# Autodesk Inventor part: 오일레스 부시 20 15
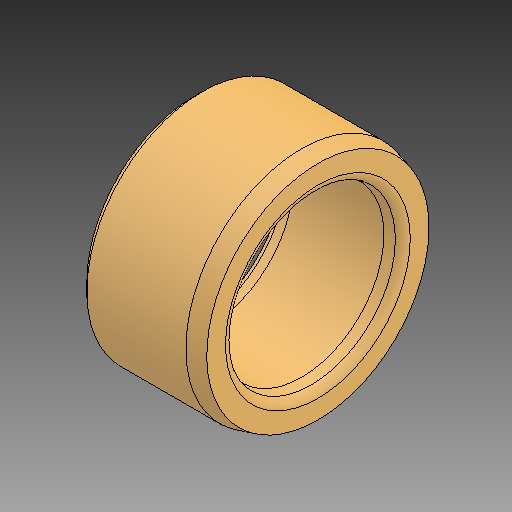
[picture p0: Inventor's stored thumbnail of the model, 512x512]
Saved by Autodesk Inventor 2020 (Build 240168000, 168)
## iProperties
Created: 2024-08
Part Number: 오일레스 부시 20 15
Material: 구리, 합금
Document SubType Name: Modeling
Designer: 1강의실14
Density: 8.92 g/cm^3
Appearance: 기본값
Author: jhkim
Sending System: Autodesk Inventor 2025
Preprocessor: ST-DEVELOPER v20
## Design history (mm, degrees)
feature "솔리드1"
node "솔리드2"
